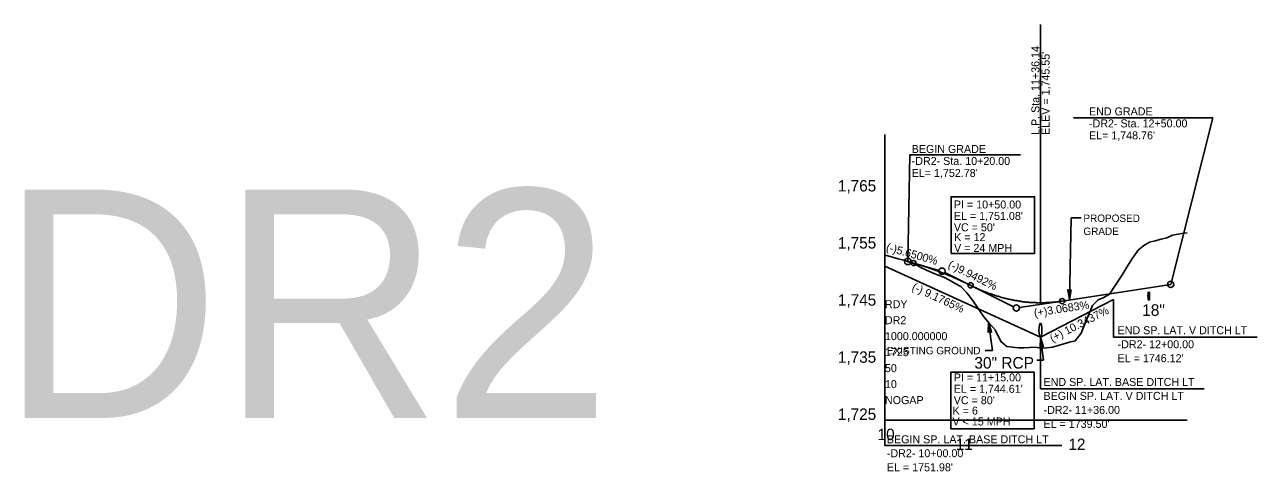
# Model space of a CAD drawing. Extents: x 498575 to 532350, y 405181 to 484585.
# Drawn here: x 526531 to 527610, y 478446 to 478837 of the extents above; entities that cross this region are included whole.
import ezdxf

# ---------------------------------------------------------------- set-up
doc = ezdxf.new("R2010")
doc.units = 0
for name, color, linetype in [('Exist Profile Cell', 7, 'Continuous'), ('Exist Vertical Profile Ground Line', 7, 'Continuous'), ('Exist Vertical Profile Horizontal Axis Label Major', 7, 'Continuous'), ('Exist Vertical Profile Vertical Axis Label', 7, 'Continuous'), ('Prop Drainage Structure Pipe Welded Steel 54in Label', 7, 'Continuous'), ('Prop Grid Mask', 7, 'Continuous'), ('Prop PFL Text', 7, 'Continuous'), ('Prop Vertical Profile Curve Label', 7, 'Continuous'), ('Prop Vertical Profile Ditch Grade Left', 7, 'Continuous'), ('Prop Vertical Profile Ditch Grade Left Label', 7, 'Continuous'), ('Prop Vertical Profile Grade', 7, 'Continuous'), ('Prop Vertical Profile Grade Label', 7, 'Continuous'), ('Prop Vertical Profile Strip Grade', 7, 'Continuous'), ('Prop VPI Label', 7, 'Continuous'), ('Scratch_Level_7', 7, 'Continuous')]:
    doc.layers.add(name, color=color, linetype=linetype)

msp = doc.modelspace()

# ---------------------------------------------------------------- linework, layer by layer
at = {"layer": 'Exist Profile Cell'}
for q in [(527283.8, 478741.2), (527548.1, 478491.2), (527283.8, 478491.2)]:
    msp.add_line((527283.8, 478491.2), q, dxfattribs=at)
at = {"layer": 'Exist Vertical Profile Ground Line'}
msp.add_lwpolyline([(527283.8, 478635.6), (527285.3, 478635.3), (527290.3, 478634), (527295.3, 478632.3), (527300.3, 478631.1), (527305.3, 478629.6), (527310.3, 478627.6), (527315.3, 478624.9), (527320.3, 478622.5), (527325.3, 478620.3), (527330.3, 478618.2), (527335.3, 478616.4), (527340.3, 478613.6), (527345.3, 478610.8), (527350.3, 478608.2), (527355.3, 478602.6), (527360.3, 478596.3), (527365.3, 478588.9), (527370.3, 478581.6), (527375.3, 478575.8), (527380.3, 478570.1), (527385.3, 478560), (527390.3, 478555.6), (527395.3, 478555.2), (527400.3, 478554.6), (527405.3, 478554.5), (527410.3, 478554.9), (527415.3, 478555), (527420.3, 478554.1), (527425.3, 478554.4), (527430.3, 478555.2), (527435.3, 478556.5), (527440.3, 478558.1), (527445.3, 478559.4), (527450.3, 478560.5), (527455.3, 478567.3), (527460.3, 478579.5), (527465.3, 478591.6), (527470.3, 478596.5), (527475.3, 478598.6), (527480.3, 478601.4), (527485.3, 478609), (527490.3, 478617), (527495.3, 478625.1), (527500.3, 478633), (527505.3, 478640), (527510.3, 478644.1), (527515.3, 478647.1), (527520.3, 478648.2), (527525.3, 478649.6), (527530.3, 478650.9), (527535.3, 478653.1), (527540.3, 478654.1), (527545.3, 478654.9), (527548.1, 478655.3)], dxfattribs=at)
at = {"layer": 'Prop Drainage Structure Pipe Welded Steel 54in Label'}
for p, q in [((527419.8, 478563.7), (527422.6, 478543.6)), ((527422.6, 478543.6), (527416.7, 478543.6))]:
    msp.add_line(p, q, dxfattribs=at)
msp.add_lwpolyline([(527422.6, 478555), (527419.8, 478563.7), (527419.5, 478554.5), (527420.9, 478555.9)], close=True, dxfattribs=at)
for centre, major_axis in [((527514.6, 478599.9), (0, 3.75)), ((527419.8, 478569.9), (0, 6.25))]:
    msp.add_ellipse(centre, major_axis=major_axis, ratio=0.2, dxfattribs=at)
at = {"layer": 'Prop Grid Mask'}
for points in [[(527341.7, 478637.2), (527414.7, 478637.2), (527414.7, 478686.7), (527341.7, 478686.7)], [(527341.3, 478483.6), (527414.3, 478483.6), (527414.3, 478533.1), (527341.3, 478533.1)]]:
    msp.add_lwpolyline(points, close=True, dxfattribs=at)
at = {"layer": 'Prop PFL Text'}
for p, q in [((527445.1, 478596.4), (527446.8, 478668.3)), ((527455.3, 478668.3), (527446.8, 478668.3)), ((527377.8, 478552.1), (527374.3, 478576.9)), ((527371.5, 478552.1), (527377.8, 478552.1))]:
    msp.add_line(p, q, dxfattribs=at)
for points in [[(527446.8, 478605.3), (527445.1, 478596.4), (527443.7, 478605.4), (527445.3, 478604.3)], [(527374, 478567.8), (527374.3, 478576.9), (527377.1, 478568.2), (527375.4, 478569.1)]]:
    msp.add_lwpolyline(points, close=True, dxfattribs=at)
at = {"layer": 'Prop Vertical Profile Curve Label'}
for centre in [(527308.8, 478628.7), (527358.8, 478609.2), (527438.8, 478595.4)]:
    msp.add_circle(centre, 2.25, dxfattribs=at)
at = {"layer": 'Prop Vertical Profile Ditch Grade Left'}
msp.add_lwpolyline([(527283.8, 478626.1), (527419.8, 478563.7), (527483.8, 478596.8)], dxfattribs=at)
at = {"layer": 'Prop Vertical Profile Ditch Grade Left Label'}
for p, q in [((527283.8, 478626.1), (527283.8, 478469)), ((527483.8, 478596.8), (527483.8, 478563.8)), ((527419.8, 478563.7), (527419.8, 478518.6)), ((527483.8, 478563.8), (527609.5, 478563.8)), ((527419.8, 478518.6), (527562.9, 478518.6)), ((527283.8, 478469), (527438.4, 478469))]:
    msp.add_line(p, q, dxfattribs=at)
at = {"layer": 'Prop Vertical Profile Grade'}
for p, q in [((527303.8, 478630.1), (527308.8, 478628.7)), ((527438.8, 478595.4), (527533.8, 478610))]:
    msp.add_line(p, q, dxfattribs=at)
for points in [[(527308.8, 478628.7), (527309.8, 478628.4), (527310.8, 478628.1), (527311.8, 478627.8), (527312.8, 478627.5), (527313.8, 478627.2), (527314.8, 478626.9), (527315.8, 478626.6), (527316.8, 478626.3), (527317.8, 478625.9), (527318.8, 478625.6), (527319.8, 478625.3), (527320.8, 478625), (527321.8, 478624.6), (527322.8, 478624.3), (527323.8, 478623.9), (527324.8, 478623.6), (527325.8, 478623.2), (527326.8, 478622.9), (527327.8, 478622.5), (527328.8, 478622.1), (527329.8, 478621.8), (527330.8, 478621.4), (527331.8, 478621), (527332.8, 478620.6), (527333.8, 478620.2), (527334.8, 478619.9), (527335.8, 478619.5), (527336.8, 478619.1), (527337.8, 478618.7), (527338.8, 478618.2), (527339.8, 478617.8), (527340.8, 478617.4), (527341.8, 478617), (527342.8, 478616.6), (527343.8, 478616.1), (527344.8, 478615.7), (527345.8, 478615.3), (527346.8, 478614.8), (527347.8, 478614.4), (527348.8, 478613.9), (527349.8, 478613.5), (527350.8, 478613), (527351.8, 478612.5), (527352.8, 478612.1), (527353.8, 478611.6), (527354.8, 478611.1), (527355.8, 478610.6), (527356.8, 478610.1), (527357.8, 478609.6), (527358.8, 478609.2)], [(527358.8, 478609.2), (527360.4, 478608.4), (527362, 478607.6), (527363.6, 478606.9), (527365.2, 478606.1), (527366.8, 478605.4), (527368.4, 478604.8), (527370, 478604.1), (527371.6, 478603.5), (527373.2, 478602.8), (527374.8, 478602.2), (527376.4, 478601.7), (527378, 478601.1), (527379.6, 478600.6), (527381.2, 478600), (527382.8, 478599.6), (527384.4, 478599.1), (527386, 478598.6), (527387.6, 478598.2), (527389.2, 478597.8), (527390.8, 478597.4), (527392.4, 478597), (527394, 478596.7), (527395.6, 478596.4), (527397.2, 478596), (527398.8, 478595.8), (527400.4, 478595.5), (527402, 478595.3), (527403.6, 478595), (527405.2, 478594.8), (527406.8, 478594.6), (527408.4, 478594.5), (527410, 478594.3), (527411.6, 478594.2), (527413.2, 478594.1), (527414.8, 478594.1), (527416.4, 478594), (527418, 478594), (527419.6, 478593.9), (527421.2, 478594), (527422.8, 478594), (527424.4, 478594), (527426, 478594.1), (527427.6, 478594.2), (527429.2, 478594.3), (527430.8, 478594.4), (527432.4, 478594.6), (527434, 478594.7), (527435.6, 478594.9), (527437.2, 478595.2), (527438.8, 478595.4)]]:
    msp.add_spline(points, degree=3, dxfattribs=at)
at = {"layer": 'Prop Vertical Profile Strip Grade'}
for p, q in [((527419.9, 478837.5), (527419.9, 478637.2)), ((527419.9, 478637.2), (527419.9, 478593.9))]:
    msp.add_line(p, q, dxfattribs=at)
at = {"layer": 'Prop VPI Label'}
for p, q in [((527448.8, 478755.8), (527570.7, 478755.8)), ((527570.7, 478755.8), (527534, 478610)), ((527305.7, 478723.6), (527303.8, 478630.2)), ((527305.7, 478723.6), (527402.4, 478723.6)), ((527308.8, 478628.7), (527331.1, 478622.3)), ((527358.8, 478609.2), (527336.3, 478620.4)), ((527358.8, 478609.2), (527396.3, 478590.5)), ((527438.8, 478595.4), (527401.5, 478589.7))]:
    msp.add_line(p, q, dxfattribs=at)
for centre in [(527303.8, 478630.1), (527333.8, 478621.6), (527533.8, 478610), (527398.8, 478589.3)]:
    msp.add_circle(centre, 2.75, dxfattribs=at)

# ---------------------------------------------------------------- texts
at = {"layer": 'Exist Profile Cell'}
for s, p in [('RDY', (527283.8, 478589.2)), ('DR2', (527283.8, 478575.2)), ('1000.000000', (527283.8, 478561.2)), ('1725', (527283.8, 478547.2)), ('50', (527283.8, 478533.2)), ('10', (527283.8, 478519.2)), ('NOGAP', (527283.8, 478505.2))]:
    msp.add_text(s, height=7, dxfattribs=at).set_placement(p)
at = {"layer": 'Exist Vertical Profile Horizontal Axis Label Major'}
for s, p in [('10', (527277.4, 478473.7)), ('11', (527345.8, 478465)), ('12', (527444.3, 478465))]:
    msp.add_text(s, height=10, dxfattribs=at).set_placement(p)
at = {"layer": 'Exist Vertical Profile Vertical Axis Label'}
for s, p in [('1,765', (527242.7, 478691.4)), ('1,755', (527242.7, 478641.4)), ('1,745', (527242.7, 478591.4)), ('1,735', (527242.7, 478541.4)), ('1,725', (527242.7, 478491.4))]:
    msp.add_text(s, height=10, dxfattribs=at).set_placement(p)
at = {"layer": 'Prop Drainage Structure Pipe Welded Steel 54in Label'}
for s, p in [('18"', (527508.8, 478582.5)), ('30" RCP', (527362, 478536.3))]:
    msp.add_text(s, height=10.12, dxfattribs=at).set_placement(p)
at = {"layer": 'Prop PFL Text'}
for s, height, p in [('PROPOSED', 6.52, (527457.4, 478664.7)), ('GRADE', 6.52, (527457.4, 478653.3)), ('EXISTING GROUND', 6.516, (527285.6, 478548.8))]:
    msp.add_text(s, height=height, dxfattribs=at).set_placement(p)
at = {"layer": 'Prop Vertical Profile Curve Label'}
for s, p in [("VC = 50'", (527344.1, 478656.5)), ('V = 24 MPH ', (527344.3, 478638.4)), ('K = 12', (527344.4, 478647.9)), ("VC = 80'", (527344, 478505.1)), ('K = 6', (527343, 478496)), ('V < 15 MPH ', (527342.9, 478486.5))]:
    msp.add_text(s, height=7, dxfattribs=at).set_placement(p)
at = {"layer": 'Prop Vertical Profile Ditch Grade Left Label'}
for s, rotation, p in [('(-) 9.1765%', 335.1959, (527306.8, 478605.4)), ('(+) 10.3437%', 27.1546, (527430.2, 478559.2)), ('END SP. LAT. V DITCH LT', 360, (527487.3, 478566.4)), ('-DR2- 12+00.00', 360, (527487.3, 478554.1)), ("EL = 1746.12'", 360, (527487.3, 478541.9)), ('END SP. LAT. BASE DITCH LT', 360, (527422.5, 478521.1)), ('BEGIN SP. LAT. V DITCH LT', 360, (527422.5, 478508.9)), ('-DR2- 11+36.00', 360, (527422.5, 478496.6)), ("EL = 1739.50'", 360, (527422.5, 478484.4)), ('BEGIN SP. LAT. BASE DITCH LT', 360, (527285.5, 478470.9)), ('-DR2- 10+00.00', 360, (527285.5, 478458.7)), ("EL = 1751.98'", 360, (527285.5, 478446.4))]:
    msp.add_text(s, height=7, rotation=rotation, dxfattribs=at).set_placement(p)
at = {"layer": 'Prop Vertical Profile Grade Label'}
for s, rotation, p in [('(-)5.6500%', 344.225, (527284.3, 478639.6)), ('(-)9.9492%', 333.5514, (527338.4, 478625.2)), ('(+)3.0683%', 8.7221, (527414.7, 478581.6))]:
    msp.add_text(s, height=7, rotation=rotation, dxfattribs=at).set_placement(p)
at = {"layer": 'Prop Vertical Profile Strip Grade'}
for s, p in [('L.P. Sta. 11+36.14', (527418.9, 478740.9)), ("ELEV = 1,745.55'", (527427.8, 478740.9))]:
    msp.add_text(s, height=7, rotation=90, dxfattribs=at).set_placement(p)
at = {"layer": 'Prop VPI Label'}
for s, p in [('END GRADE', (527462.3, 478758)), ('-DR2- Sta. 12+50.00', (527462.3, 478747.5)), ("EL= 1,748.76'", (527462.3, 478737)), ('BEGIN GRADE', (527307.2, 478725.1)), ('-DR2- Sta. 10+20.00', (527307.2, 478714.6)), ("EL= 1,752.78'", (527307.2, 478704.1)), ('PI = 10+50.00', (527344.1, 478676.5)), ("EL = 1,751.08'", (527344.1, 478666.5)), ('PI = 11+15.00', (527344, 478525.1)), ("EL = 1,744.61'", (527344, 478515.1))]:
    msp.add_text(s, height=7, dxfattribs=at).set_placement(p)
at = {"layer": 'Scratch_Level_7'}
msp.add_text('DR2', height=200, dxfattribs=at).set_placement((526509.4, 478493.1))

doc.saveas('drawing.dxf')
